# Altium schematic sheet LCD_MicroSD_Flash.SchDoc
size A4; Revision: C.2
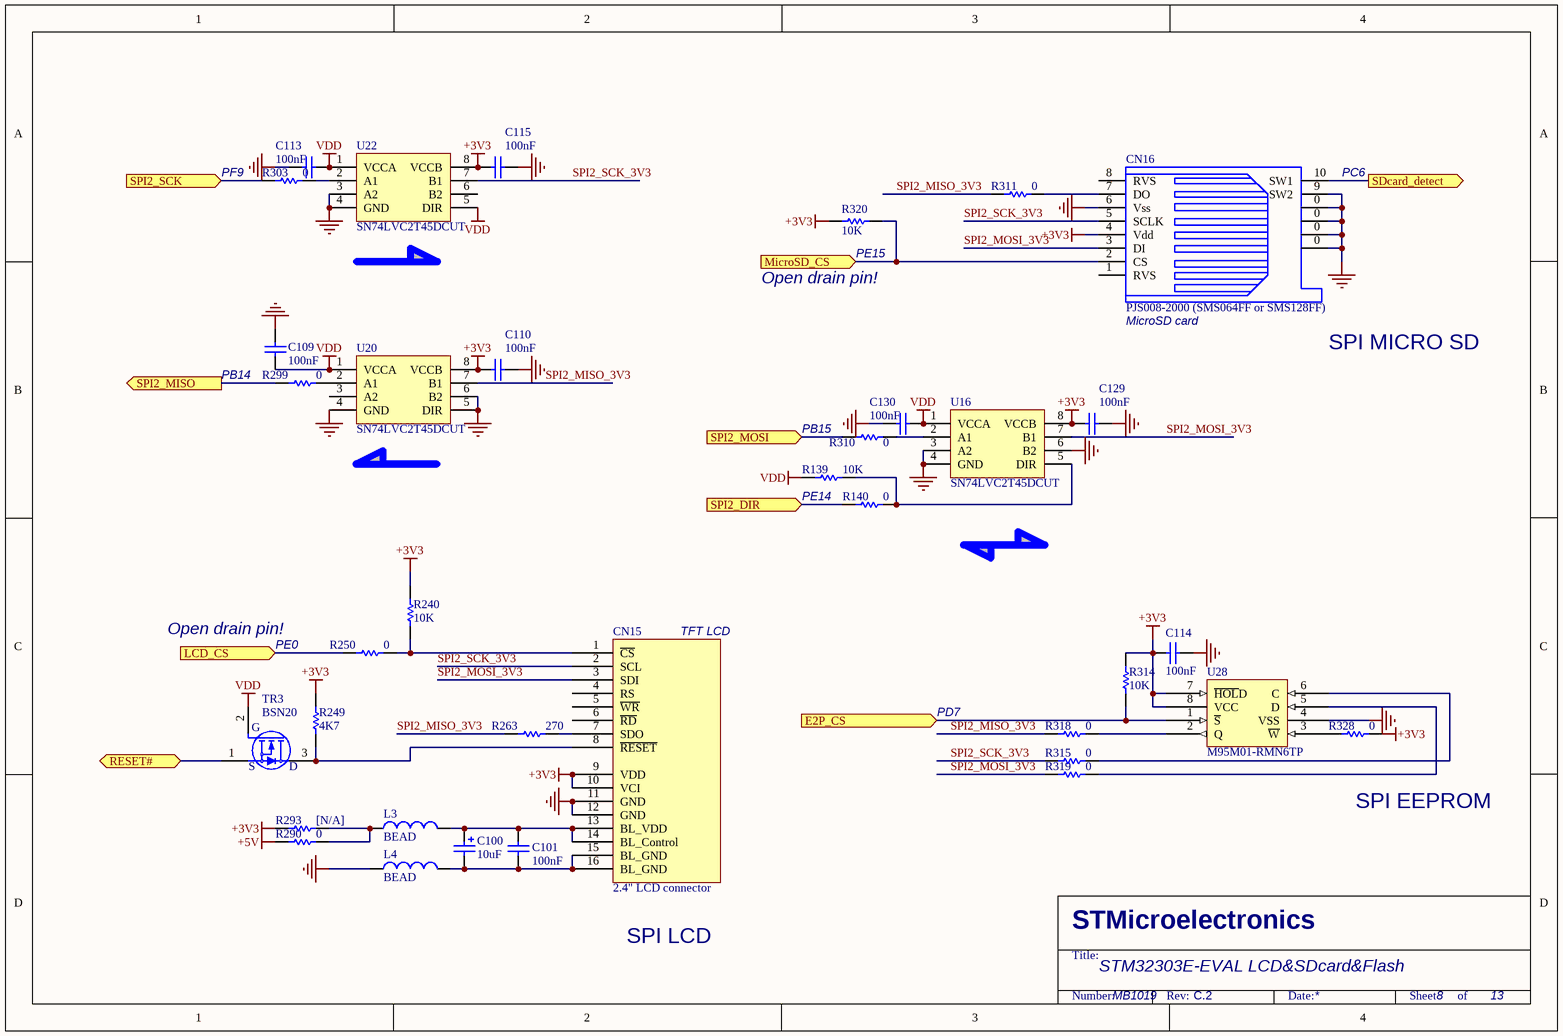
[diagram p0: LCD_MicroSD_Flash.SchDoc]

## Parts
C100  10uF  [TAN-A]
C101  100nF  [0603C]
C109  100nF  [0603C]
C110  100nF  [0603C]
C113  100nF  [0603C]
C114  100nF  [0603C]
C115  100nF  [0603C]
C129  100nF  [0603C]
C130  100nF  [0603C]
CN15  2.4" LCD connector  [MB895CS]
CN16  PJS008-2000 (SMS064FF or SMS128FF)  [MSD(PJS008)]
L3  BEAD  [0603L]
L4  BEAD  [0603L]
R139  10K  [0603R]
R140  0  [0603R]
R240  10K  [0603R]
R249  4K7  [0603R]
R250  0  [0603R]
R263  270  [0603R]
R290  0  [0603R]
R293  [N/A]  [0603R]
R299  0  [0603R]
R303  0  [0603R]
R310  0  [0603R]
R311  0  [0603R]
R314  10K  [0603R]
R315  0  [0603R]
R318  0  [0603R]
R319  0  [0603R]
R320  10K  [0603R]
R328  0  [0603R]
TR3  BSN20  [SOT-23]
U16  SN74LVC2T45DCUT  [VSSOP8]
U20  SN74LVC2T45DCUT  [VSSOP8]
U22  SN74LVC2T45DCUT  [VSSOP8]
U28  M95M01-RMN6TP  [SO8]

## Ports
E2P_CS (in), LCD_CS (in), MicroSD_CS (in), RESET# (bidir), SDcard_detect (out), SPI2_DIR (in), SPI2_MISO (out), SPI2_MOSI (in), SPI2_SCK (in)

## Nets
+3V3: C110.2 C114.1 C115.2 C129.2 CN15.9(VDD) CN15.10(VCI) CN16.4(Vdd) R240.2 R249.2 R293.1 R314.1 R320.2 R328.1 U16.8(VCCB) U20.8(VCCB) U22.8(VCCB) U28.7(~{HOL}D) U28.8(VCC)
+5V: R290.1
GND: C109.1 C110.1 C113.1 C114.2 C115.1 C129.1 C130.1 CN15.11(GND) CN15.12(GND) CN16.0 CN16.6(Vss) CN16.9(SW2) L4.1 U16.3(A2) U16.4(GND) U16.6(B2) U20.4(GND) U20.5(DIR) U20.6(B2) U22.3(A2) U22.4(GND) U28.4(VSS)
VDD: C109.2 C113.2 C130.2 R139.2 TR3.2(G) U16.1(VCCA) U20.1(VCCA) U22.1(VCCA) U22.5(DIR)
E2P_CS: R314.2 U28.1(~{S}) ; port E2P_CS
LCD_CS: R250.1 ; port LCD_CS
MicroSD_CS: CN16.2(CS) R320.1 ; port MicroSD_CS
RESET#: TR3.1(S) ; port RESET#
SDcard_detect: CN16.10(SW1) ; port SDcard_detect
SPI2_DIR: R140.2 ; port SPI2_DIR
SPI2_MISO: R299.1 ; port SPI2_MISO
SPI2_MISO_3V3: R263.1 R311.1 R318.2 U20.7(B1)
SPI2_MOSI: R310.2 ; port SPI2_MOSI
SPI2_MOSI_3V3: CN15.3(SDI) CN16.3(DI) R319.2 U16.7(B1)
SPI2_SCK: R303.2 ; port SPI2_SCK
SPI2_SCK_3V3: CN15.2(SCL) CN16.5(SCLK) R315.2 U22.7(B1)
NetC100_1: C100.1 C101.1 CN15.13(BL_VDD) CN15.14(BL_Control) L3.2
NetC100_2: C100.2 C101.2 CN15.15(BL_GND) CN15.16(BL_GND) L4.2
NetCN15_1: CN15.1(~{CS}) R240.1 R250.2
NetCN15_7: CN15.7(SDO) R263.2
NetCN15_8: CN15.8(~{RESET}) R249.1 TR3.3(D)
NetCN16_7: CN16.7(DO) R311.2
NetL3_1: L3.1 R290.2 R293.2
NetR139_1: R139.1 R140.1 U16.5(DIR)
NetR299_2: R299.2 U20.2(A1)
NetR303_1: R303.1 U22.2(A1)
NetR310_1: R310.1 U16.2(A1)
NetR315_1: R315.1 U28.6(C)
NetR318_1: R318.1 U28.2(Q)
NetR319_1: R319.1 U28.5(D)
NetR328_2: R328.2 U28.3(~{W})

Not connected (* = marked no-connect by the designer): CN15 4(RS) 5(~{WR}) 6(~{RD}); CN16 1(RVS) 8(RVS); U20 3(A2); U22 6(B2)

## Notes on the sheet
- (near R303) PF9
- (near CN16) PC6
- (near R320) Open drain pin!
- (near R320) PE15
- PB14
- (near CN16) MicroSD card
- SPI MICRO SD
- PB15
- (near R139) PE14
- Open drain pin!
- PE0
- TFT LCD
- PD7
- SPI EEPROM
- SPI LCD
- STM32303E-EVAL LCD&SDcard&Flash
- MB1019
- 8
- 13

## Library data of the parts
C100 = Cap Pol1: Polarized Capacitor (Radial)
C101 C114 = Cap: Capacitor; Value: 10nF
C109 C110 C113 C115 C129 C130 = CAP: Capacitor; Value: 100pF
CN15 = ColorLCD_module
CN16 = SMS016AFA5E
L3 L4 = Inductor: Value: 100uH
R139 R140 R240 R249 R250 R263 R290 R293 R299 R311 R315 R318-R320 R328 = Res1: Resistor; Value: 1K
R303 R310 R314 = res1: Resistor; Value: 1K
TR3 = 2N7000
U28 = M95040-R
